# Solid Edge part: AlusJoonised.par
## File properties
Author: Egon 815
Template: Normal.par
Last saved by: Egon 815
Revision: 97
Application: Solid Edge
Accuracy: 0,990
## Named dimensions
RefPlane_22: Distance = 42000 mm
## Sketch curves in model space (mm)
line (0, 3037.3995, 23860.165) -> (0, 3037.3995, 8314.9532)
line (0, -4351.2813, 23860.165) -> (0, -4351.2813, 8314.9532)
line (0, -4351.2813, 23860.165) -> (0, 3037.3995, 23860.165)
arc centre (-893.7083, -1487.539, 8310) radius 2000 from (-2893.7083, -1487.539, 8310) through (-2266.1916, -2942.2863, 8310) to (-893.7083, -3487.539, 8310)
line (893.7083, -3487.539, 8310) -> (-893.7083, -3487.539, 8310)
arc centre (893.7083, -1487.539, 8310) radius 2000 from (893.7083, -3487.539, 8310) through (2348.4556, -2860.0223, 8310) to (2893.7083, -1487.539, 8310)
line (2893.7083, 1010.2748, 8310) -> (2893.7083, -1487.539, 8310)
arc centre (893.7083, 1010.2748, 8310) radius 2000 from (893.7083, 3010.2748, 8310) through (2348.4556, 2382.758, 8310) to (2893.7083, 1010.2748, 8310)
line (-893.7083, 3010.2748, 8310) -> (893.7083, 3010.2748, 8310)
arc centre (-893.7083, 1010.2748, 8310) radius 2000 from (-2893.7083, 1010.2748, 8310) through (-2266.1916, 2465.022, 8310) to (-893.7083, 3010.2748, 8310)
line (-2893.7083, 1010.2748, 8310) -> (-2893.7083, -1487.539, 8310)
line (-4658.2982, 0, 17061.7126) -> (-4658.2982, 0, 22614.5062)
line (-4658.2982, 0, 22614.5062) -> (4630.011, 0, 22614.5062)
line (4630.011, 0, 22614.5062) -> (4630.011, 0, 17061.7126)
line (4630.011, 0, 17061.7126) -> (-4658.2982, 0, 17061.7126)
line (-2437.1808, 0, 27536.3004) -> (2358.4137, 0, 27536.3004)
line (2358.4137, 0, 27536.3004) -> (2358.4137, 0, 22614.5062)
line (-2437.1808, 0, 22614.5062) -> (2358.4137, 0, 22614.5062)
line (-2437.1808, 0, 22614.5062) -> (-2437.1808, 0, 27536.3004)
line (-1478.0619, 0, 31221.3362) -> (1575.9746, 0, 31221.3362)
line (1575.9746, 0, 31221.3362) -> (1575.9746, 0, 27536.3004)
line (-1478.0619, 0, 27536.3004) -> (1575.9746, 0, 27536.3004)
line (-1478.0619, 0, 27536.3004) -> (-1478.0619, 0, 31221.3362)
line (0, -58110, -8419.563) -> (0, -100110, -6634.2763)
arc centre (0, -94180.934, 9804.7076) radius 17475.5262 from (0, -100110, -6634.2763) through (0, -108038.3579, -842.631) to (0, -111592.4206, 8310)
line (0, -111592.4206, 8310) -> (0, -58110, 8310)
line (0, -58110, 8310) -> (0, -58110, -8419.563)
line (0, 58110, 0) -> (0, 121328.7038, 0)
arc centre (0, -94180.934, 9804.7076) radius 17475.5262 from (0, -100110, -6634.2763) through (0, -108038.3579, -842.631) to (0, -111592.4206, 8310)
arc centre (0, -66819.8022, 281607.7742) radius 290158.0896 from (0, -58110, -8419.563) through (0, -79142.3739, -8288.5369) to (0, -100110, -6634.2763)
spline (0, 108319.1409, -466.861) -> (0, 87426.5717, -1716.8383) -> (0, 74368.3125, -7728.4737)
spline (0, 111888.0426, 5818.6126) -> (0, 79249.523, -627.6963) -> (0, 61996.5318, -8357.1547)
spline (0, -111592.4206, 8310) -> (6396.3752, -95897.2038, 8310) -> (11499.3187, -58110, 8310)
spline (1815.8522, -98942.7597, -627.6741) -> (2610.5873, -98942.7597, 3198.1174) -> (5698.9261, -98942.7597, 8310)
spline (0, -98942.7597, -6683.892) -> (1090.9047, -98942.7597, -4829.0549) -> (1815.8522, -98942.7597, -627.6741)
line (-5128.0164, 0, 8310) -> (5128.0164, 0, 8310)
arc centre (-22553.4282, 0, -4878.3254) radius 21853.533 from (-699.8952, 0, -4878.3254) through (-1836.4821, 0, 2077.6106) to (-5128.0164, 0, 8310)
arc centre (0, 0, -4878.3254) radius 699.8952 from (-699.8952, 0, -4878.3254) through (-480.2973, 0, -5387.4108) to (0, 0, -5578.2207)
arc centre (0, 0, -4878.3254) radius 699.8952 from (0, 0, -5578.2207) through (509.0853, 0, -5358.6227) to (699.8952, 0, -4878.3254)
arc centre (22553.4282, 0, -4878.3254) radius 21853.533 from (699.8952, 0, -4878.3254) through (1836.4821, 0, 2077.6106) to (5128.0164, 0, 8310)
line (-5128.0164, -100110, 8310) -> (5128.0164, -100110, 8310)
arc centre (-22553.4282, -100110, -4878.3254) radius 21853.533 from (-699.8952, -100110, -4878.3254) through (-1836.4821, -100110, 2077.6106) to (-5128.0164, -100110, 8310)
arc centre (0, -100110, -4878.3254) radius 699.8952 from (-699.8952, -100110, -4878.3254) through (-480.2973, -100110, -5387.4108) to (0, -100110, -5578.2207)
arc centre (0, -100110, -4878.3254) radius 699.8952 from (699.8952, -100110, -4878.3254) through (480.2973, -100110, -5387.4108) to (0, -100110, -5578.2207)
arc centre (22553.4282, -100110, -4878.3254) radius 21853.533 from (699.8952, -100110, -4878.3254) through (1836.4821, -100110, 2077.6106) to (5128.0164, -100110, 8310)
line (0, -44381.2454, 5032.5774) -> (0, 120116.3176, 5032.5774)
line (0, -44381.2454, 5032.5774) -> (0, -59033.8334, 5032.5774)
line (0, -59033.8334, 5032.5774) -> (0, -66244.3403, 7184.8312)
line (0, -111469.4186, 8314.9532) -> (0, -66244.3403, 7184.8312)
line (0, -36553.8811, 30853.7571) -> (0, -36553.8811, 25923.1734)
line (0, -37771.6996, 22633.8218) -> (0, -37771.6996, 25923.1734)
line (0, -37464.9383, 30853.7571) -> (0, -37771.6996, 25923.1734)
line (0, -28843.4594, 17243.6107) -> (0, -28843.4594, 10563.589)
line (0, -39625.8092, 17243.6107) -> (0, -28843.4594, 17243.6107)
line (0, -28843.4594, 10563.589) -> (0, -39625.8092, 10563.589)
line (0, -39625.8092, 10563.589) -> (0, -39625.8092, 17243.6107)
line (0, -28843.4594, 13000.7205) -> (0, -28843.4594, 10563.589)
line (0, -13839.988, 10563.589) -> (0, -28843.4594, 10563.589)
line (0, -13839.988, 13000.7205) -> (0, -13839.988, 10563.589)
line (0, -13839.988, 13000.7205) -> (0, -28843.4594, 13000.7205)
line (0, -31830.7277, 22633.8218) -> (0, -31830.7277, 17243.6107)
line (0, -41094.6161, 22633.8218) -> (0, -31830.7277, 22633.8218)
line (0, -41094.6161, 17243.6107) -> (0, -41094.6161, 22633.8218)
line (0, -35690.6812, 17243.6107) -> (0, -41094.6161, 17243.6107)
line (0, -33811.0517, 25923.1734) -> (0, -33811.0517, 22633.8218)
line (0, -37771.6996, 25923.1734) -> (0, -33811.0517, 25923.1734)
line (0, -29834.8339, 30853.7571) -> (0, -31827.7717, 30853.7571)
line (0, -31827.7717, 30853.7571) -> (0, -31827.7717, 17243.6107)
line (0, -31827.7717, 17243.6107) -> (0, -29834.8339, 17243.6107)
line (0, -29834.8339, 17243.6107) -> (0, -29834.8339, 30853.7571)
line (0, -37464.9383, 30853.7571) -> (0, -37464.9383, 31353.7571)
line (0, -37464.9383, 31353.7571) -> (0, -26589.1925, 31353.7571)
line (0, -26589.1925, 31353.7571) -> (0, -26589.1925, 30853.7571)
line (0, -26589.1925, 30853.7571) -> (0, -37464.9383, 30853.7571)
line (0, -5463.7623, 7184.8312) -> (0, -5463.7623, 10563.589)
line (0, -42546.9286, 10563.589) -> (0, -5463.7623, 10563.589)
line (0, -42546.9286, 10563.589) -> (0, -53131.8324, 10563.589)
line (0, -53131.8324, 7184.8312) -> (0, -53131.8324, 10563.589)
line (0, -54662.205, 8314.9532) -> (0, -54662.205, 6344.2559)
line (0, -66107.4769, 8314.9532) -> (0, -66107.4769, 6344.2559)
line (0, -66882.6547, 9878.1546) -> (0, -64602.72, 9878.1546)
line (0, -66882.6547, 9148.5755) -> (0, -66882.6547, 9878.1546)
line (0, -77940.3377, 9148.5755) -> (0, -66882.6547, 9148.5755)
line (0, -77940.3377, 8464.5951) -> (0, -66403.8684, 8314.9532)
line (0, -77940.3377, 8464.5951) -> (0, -77940.3377, 9148.5755)
line (0, -53567.8364, 8314.9532) -> (0, -66403.8684, 8314.9532)
line (0, -53567.8364, 11451.3095) -> (0, -53567.8364, 8314.9532)
line (0, -63097.9632, 10676.1317) -> (0, -53567.8364, 11451.3095)
line (0, -64602.72, 9878.1546) -> (0, -63097.9632, 10676.1317)
line (0, -66403.8684, 8601.3912) -> (0, -64602.72, 9878.1546)
line (0, -66403.8684, 8314.9532) -> (0, -66403.8684, 8601.3912)
line (0, -66403.8684, 7757.8154) -> (0, -66403.8684, 6344.2559)
line (0, -54229.0174, 7757.8154) -> (0, -54229.0174, 5842.6703)
line (0, -54229.0174, 7757.8154) -> (0, -66403.8684, 7757.8154)
circle centre (1553.0628, 0, 8932.106) radius 675.2464
circle centre (1553.0628, 0, 8932.106) radius 353.597
circle centre (1553.0628, 0, 8932.106) radius 210.8001
line (3614.1063, 0, 8472.6575) -> (3614.1063, 0, 10104.702)
line (3614.1063, 0, 10104.702) -> (0, 0, 10336.0154)
line (0, 0, 10336.0154) -> (-3620.8628, 0, 10104.702)
line (-3620.8628, 0, 10104.702) -> (-3620.8628, 0, 8472.6575)
line (-3620.8628, 0, 8472.6575) -> (3614.1063, 0, 8472.6575)
line (2817.3601, 0, 11107.0601) -> (0, 0, 11479.7317)
line (4025.3301, 0, 10104.702) -> (2817.3601, 0, 11107.0601)
line (4744.9718, 0, 9320.8066) -> (4025.3301, 0, 10104.702)
line (4744.9718, 0, 8395.553) -> (4744.9718, 0, 9320.8066)
line (4744.9718, 0, 8395.553) -> (0, 0, 8395.553)
line (2277.6289, 0, 10079.0005) -> (2277.6289, 0, 8472.6575)
line (864.047, 0, 10168.9557) -> (2277.6289, 0, 10079.0005)
line (864.047, 0, 8472.6575) -> (864.047, 0, 10168.9557)
arc centre (4185.1243, -58110, -12615.4047) radius 5926.2428 from (4371.7702, -58110, -6692.1018) through (2007.2841, -58110, -7103.8382) to (0, -58110, -8419.563)
arc centre (6098.5646, -58110, -470.8784) radius 6456.4262 from (9744.6378, -58110, -5799.2543) through (7156.9605, -58110, -6839.9629) to (4371.7702, -58110, -6692.1018)
arc centre (1803.2627, -58110, -494.6187) radius 9550.1099 from (11353.3694, -58110, -486.8867) through (10943.4649, -58110, -3262.5242) to (9744.6378, -58110, -5799.2543)
arc centre (72636.1358, -58110, 2896.0245) radius 61376.0665 from (11353.3694, -58110, -486.8867) through (11268.5148, -58110, 3914.1752) to (11499.3187, -58110, 8310)
line (-19950.5693, 0, 45450.8749) -> (-19950.5693, 0, -11537.5418)
line (19465.6098, 0, 45450.8749) -> (-19950.5693, 0, 45450.8749)
line (19465.6098, 0, -11537.5418) -> (19465.6098, 0, 45450.8749)
line (-19950.5693, 0, -11537.5418) -> (19465.6098, 0, -11537.5418)
line (0, 0, 44802.9635) -> (0, 0, -9317.0365)
line (17000, 0, 0) -> (-17000, 0, 0)
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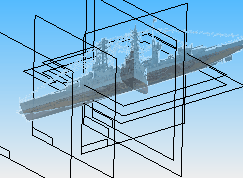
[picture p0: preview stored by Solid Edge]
